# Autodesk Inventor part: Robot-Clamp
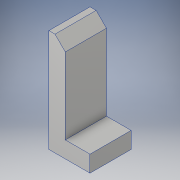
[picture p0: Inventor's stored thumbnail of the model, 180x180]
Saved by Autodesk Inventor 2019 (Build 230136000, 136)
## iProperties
Created: 2018-07
Part Number: Robot-Clamp
Material: Aluminum 6061
Description: 123456
Document SubType Name: Modeling
Designer: Power User
Mass: 26.109 g
Surface Area: 37.0842 cm^2
Volume: 9.67 cm^3
Density: 2.7 g/cm^3
Appearance: Aluminum - Flat
Author: Power User
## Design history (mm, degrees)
sketch "Sketch6"
  geometry: L1 (0, 0)-(0, 50); L2 (0, 50)-(8, 50); L3 (8, 50)-(8, 8); L4 (8, 8)-(20, 8); L5 (20, 8)-(20, 0); L6 (20, 0)-(0, 0)
  constraints: 12 end point, 5 perpendicular, 1 vertical
  dimensions: "d44" = 20 distance of L5.end L1.start; "d45" = 12 distance of L3.end L4.end; "d46" = 50 distance of L1.start L1.end; "d47" = 8 distance of L4.end L5.end
extrude "Extrusion5" new body sketch "Sketch6" stored distance "d48" = 20; taper "d49" = 0 deg
chamfer "Chamfer2" distance "d50" = 5; stored, may be unused: second distance "d51" = 5, angle "d52" = 45 deg
body "Solid2"
